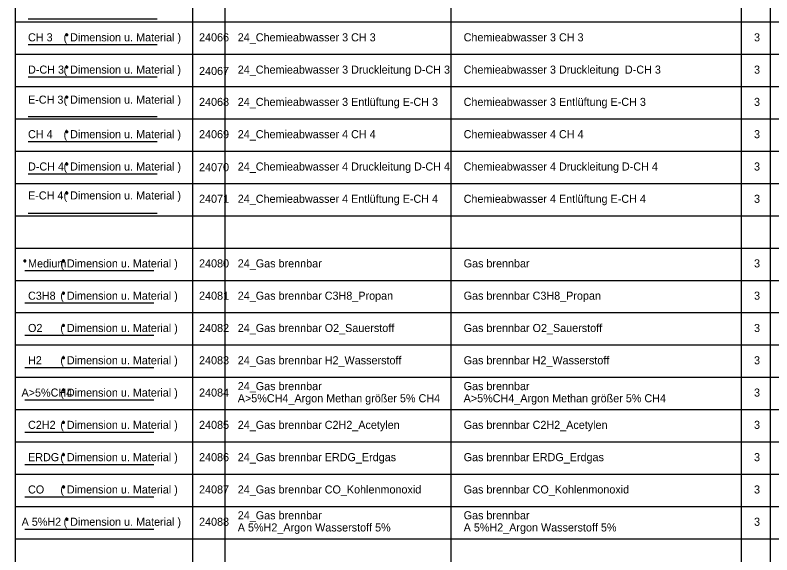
# Model space of a CAD drawing. Extents: x -14.5 to 23.8, y -56.3 to 8.
# Drawn here: x 0 to 11.73, y -23.75 to -15.39 of the extents above; entities that cross this region are included whole.
import ezdxf

# ---------------------------------------------------------------- set-up
doc = ezdxf.new("R2010")
doc.units = 0
for name, color, linetype in [('24_Chemieabwasser 2 Entlüftung E-CH2', 7, 'Continuous'), ('24_Chemieabwasser 3 CH 3', 7, 'Continuous'), ('24_Chemieabwasser 3 Druckleitung D-CH 3', 7, 'Continuous'), ('24_Chemieabwasser 3 Entlüftung E-CH 3', 7, 'Continuous'), ('24_Chemieabwasser 4 CH 4', 7, 'Continuous'), ('24_Chemieabwasser 4 Druckleitung CH 4', 7, 'Continuous'), ('24_Chemieabwasser 4 Entlüftung E-CH 4', 7, 'Continuous'), ('24_Gas brennbar', 7, 'Continuous'), ('24_Gas brennbar A 5%H2_Argon Wasserstoff 5%', 7, 'Continuous'), ('24_Gas brennbar A-5%CH4_Argon Methan größer 5% CH4', 7, 'Continuous'), ('24_Gas brennbar C2H2_Acetylen', 7, 'Continuous'), ('24_Gas brennbar C3H8_Propan', 7, 'Continuous'), ('24_Gas brennbar CO_Kohlenmonoxid', 7, 'Continuous'), ('24_Gas brennbar ERDG_Erdgas', 7, 'Continuous'), ('24_Gas brennbar H2_Wasserstoff', 7, 'Continuous'), ('24_Gas brennbar O2_Sauerstoff', 7, 'Continuous'), ('Default', 7, 'Continuous')]:
    doc.layers.add(name, color=color, linetype=linetype)

msp = doc.modelspace()

# ---------------------------------------------------------------- linework, layer by layer
at = {"layer": '24_Chemieabwasser 2 Entlüftung E-CH2'}
msp.add_line((0.2, -15.451), (2.2, -15.451), dxfattribs=at)
at = {"layer": '24_Chemieabwasser 3 CH 3'}
for p, q in [((0.778, -15.7), (0.822, -15.7)), ((0.784, -15.684), (0.816, -15.716)), ((0.816, -15.684), (0.784, -15.716)), ((0.8, -15.678), (0.8, -15.722)), ((0.2, -15.85), (2.2, -15.85)), ((0.8, -16.178), (0.8, -16.222)), ((0.778, -16.2), (0.822, -16.2)), ((0.784, -16.184), (0.816, -16.216)), ((0.816, -16.184), (0.784, -16.216))]:
    msp.add_line(p, q, dxfattribs=at)
at = {"layer": '24_Chemieabwasser 3 Druckleitung D-CH 3'}
msp.add_line((0.2, -16.35), (2.2, -16.35), dxfattribs=at)
at = {"layer": '24_Chemieabwasser 3 Entlüftung E-CH 3'}
for p, q in [((0.784, -16.649), (0.816, -16.681)), ((0.816, -16.649), (0.784, -16.681)), ((0.8, -16.643), (0.8, -16.687)), ((0.778, -16.665), (0.822, -16.665)), ((0.2, -16.961), (2.2, -16.961))]:
    msp.add_line(p, q, dxfattribs=at)
at = {"layer": '24_Chemieabwasser 4 CH 4'}
for p, q in [((0.778, -17.2), (0.822, -17.2)), ((0.784, -17.184), (0.816, -17.216)), ((0.816, -17.184), (0.784, -17.216)), ((0.8, -17.178), (0.8, -17.222)), ((0.2, -17.35), (2.2, -17.35)), ((0.778, -17.7), (0.822, -17.7))]:
    msp.add_line(p, q, dxfattribs=at)
at = {"layer": '24_Chemieabwasser 4 Druckleitung CH 4'}
for p, q in [((0.784, -17.684), (0.816, -17.716)), ((0.816, -17.684), (0.784, -17.716)), ((0.8, -17.678), (0.8, -17.722)), ((0.2, -17.85), (2.2, -17.85))]:
    msp.add_line(p, q, dxfattribs=at)
at = {"layer": '24_Chemieabwasser 4 Entlüftung E-CH 4'}
for p, q in [((0.778, -18.148), (0.822, -18.148)), ((0.784, -18.133), (0.816, -18.164)), ((0.816, -18.133), (0.784, -18.164)), ((0.8, -18.126), (0.8, -18.17)), ((0.2, -18.458), (2.2, -18.458))]:
    msp.add_line(p, q, dxfattribs=at)
at = {"layer": '24_Gas brennbar'}
for p, q in [((0.128, -19.2), (0.172, -19.2)), ((0.134, -19.184), (0.166, -19.216)), ((0.166, -19.184), (0.134, -19.216)), ((0.15, -19.178), (0.15, -19.222)), ((0.728, -19.2), (0.772, -19.2)), ((0.734, -19.184), (0.766, -19.216)), ((0.766, -19.184), (0.734, -19.216)), ((0.75, -19.178), (0.75, -19.222)), ((0.15, -19.35), (2.15, -19.35))]:
    msp.add_line(p, q, dxfattribs=at)
at = {"layer": '24_Gas brennbar A 5%H2_Argon Wasserstoff 5%'}
for p, q in [((0.778, -23.2), (0.822, -23.2)), ((0.784, -23.184), (0.816, -23.216)), ((0.816, -23.184), (0.784, -23.216)), ((0.8, -23.178), (0.8, -23.222)), ((0.15, -23.35), (2.15, -23.35))]:
    msp.add_line(p, q, dxfattribs=at)
at = {"layer": '24_Gas brennbar A-5%CH4_Argon Methan größer 5% CH4'}
for p, q in [((0.729, -21.2), (0.773, -21.2)), ((0.735, -21.184), (0.767, -21.216)), ((0.767, -21.184), (0.735, -21.216)), ((0.751, -21.178), (0.751, -21.222)), ((0.15, -21.35), (2.15, -21.35))]:
    msp.add_line(p, q, dxfattribs=at)
at = {"layer": '24_Gas brennbar C2H2_Acetylen'}
for p, q in [((0.734, -21.684), (0.766, -21.716)), ((0.766, -21.684), (0.734, -21.716)), ((0.75, -21.678), (0.75, -21.722)), ((0.728, -21.7), (0.772, -21.7)), ((0.15, -21.85), (2.15, -21.85))]:
    msp.add_line(p, q, dxfattribs=at)
at = {"layer": '24_Gas brennbar C3H8_Propan'}
for p, q in [((0.728, -19.7), (0.772, -19.7)), ((0.734, -19.684), (0.766, -19.716)), ((0.766, -19.684), (0.734, -19.716)), ((0.75, -19.678), (0.75, -19.722)), ((0.15, -19.85), (2.15, -19.85))]:
    msp.add_line(p, q, dxfattribs=at)
at = {"layer": '24_Gas brennbar CO_Kohlenmonoxid'}
for p, q in [((0.728, -22.7), (0.772, -22.7)), ((0.734, -22.684), (0.766, -22.716)), ((0.766, -22.684), (0.734, -22.716)), ((0.75, -22.678), (0.75, -22.722)), ((0.15, -22.85), (2.15, -22.85))]:
    msp.add_line(p, q, dxfattribs=at)
at = {"layer": '24_Gas brennbar ERDG_Erdgas'}
for p, q in [((0.728, -22.2), (0.772, -22.2)), ((0.734, -22.184), (0.766, -22.216)), ((0.766, -22.184), (0.734, -22.216)), ((0.75, -22.178), (0.75, -22.222)), ((0.15, -22.35), (2.15, -22.35))]:
    msp.add_line(p, q, dxfattribs=at)
at = {"layer": '24_Gas brennbar H2_Wasserstoff'}
for p, q in [((0.728, -20.7), (0.772, -20.7)), ((0.734, -20.684), (0.766, -20.716)), ((0.766, -20.684), (0.734, -20.716)), ((0.75, -20.678), (0.75, -20.722)), ((0.15, -20.85), (2.15, -20.85))]:
    msp.add_line(p, q, dxfattribs=at)
at = {"layer": '24_Gas brennbar O2_Sauerstoff'}
for p, q in [((0.728, -20.2), (0.772, -20.2)), ((0.734, -20.184), (0.766, -20.216)), ((0.766, -20.184), (0.734, -20.216)), ((0.75, -20.178), (0.75, -20.222)), ((0.15, -20.35), (2.15, -20.35))]:
    msp.add_line(p, q, dxfattribs=at)
at = {"layer": 'Default'}
for p, q in [((0, 0), (0, -53.5)), ((2.75, 0), (2.75, -53.5)), ((3.25, 0), (3.25, -53.5)), ((6.75, 0), (6.75, -53.5)), ((11.25, 0), (11.25, -53.5)), ((11.7, -0.35), (11.7, -44.5)), ((0, -15.5), (16, -15.5)), ((0, -16), (16, -16)), ((0, -16.5), (16, -16.5)), ((0, -17), (16, -17)), ((0, -17.5), (16, -17.5)), ((0, -18), (16, -18)), ((0, -18.5), (16, -18.5)), ((0, -19), (16, -19)), ((0, -19.5), (16, -19.5)), ((0, -20), (16, -20)), ((0, -20.5), (16, -20.5)), ((0, -21), (16, -21)), ((0, -21.5), (16, -21.5)), ((0, -22), (16, -22)), ((0, -22.5), (16, -22.5)), ((0, -23), (16, -23)), ((0, -23.5), (16, -23.5))]:
    msp.add_line(p, q, dxfattribs=at)

# ---------------------------------------------------------------- texts
at = {"layer": '24_Chemieabwasser 3 CH 3'}
for s, p in [('CH 3', (0.2, -15.8)), ('( Dimension u. Material )', (0.75, -15.8))]:
    msp.add_text(s, height=0.125, dxfattribs=at).set_placement(p)
at = {"layer": '24_Chemieabwasser 3 Druckleitung D-CH 3'}
for s, p in [('D-CH 3', (0.2, -16.3)), ('( Dimension u. Material )', (0.75, -16.3))]:
    msp.add_text(s, height=0.125, dxfattribs=at).set_placement(p)
at = {"layer": '24_Chemieabwasser 3 Entlüftung E-CH 3'}
for s, p in [('E-CH 3', (0.2, -16.765)), ('( Dimension u. Material )', (0.75, -16.765))]:
    msp.add_text(s, height=0.125, dxfattribs=at).set_placement(p)
at = {"layer": '24_Chemieabwasser 4 CH 4'}
for s, p in [('CH 4', (0.2, -17.3)), ('( Dimension u. Material )', (0.75, -17.3))]:
    msp.add_text(s, height=0.125, dxfattribs=at).set_placement(p)
at = {"layer": '24_Chemieabwasser 4 Druckleitung CH 4'}
for s, p in [('D-CH 4', (0.2, -17.8)), ('( Dimension u. Material )', (0.75, -17.8))]:
    msp.add_text(s, height=0.125, dxfattribs=at).set_placement(p)
at = {"layer": '24_Chemieabwasser 4 Entlüftung E-CH 4'}
for s, p in [('E-CH 4', (0.2, -18.248)), ('( Dimension u. Material )', (0.75, -18.248))]:
    msp.add_text(s, height=0.125, dxfattribs=at).set_placement(p)
at = {"layer": '24_Gas brennbar'}
for s, p in [('Medium', (0.2, -19.3)), ('( Dimension u. Material )', (0.7, -19.3))]:
    msp.add_text(s, height=0.125, dxfattribs=at).set_placement(p)
at = {"layer": '24_Gas brennbar A 5%H2_Argon Wasserstoff 5%'}
for s, p in [('A 5%H2', (0.1, -23.3)), ('( Dimension u. Material )', (0.75, -23.3))]:
    msp.add_text(s, height=0.125, dxfattribs=at).set_placement(p)
at = {"layer": '24_Gas brennbar A-5%CH4_Argon Methan größer 5% CH4'}
for s, p in [('A>5%CH4', (0.099, -21.3)), ('( Dimension u. Material )', (0.7, -21.3))]:
    msp.add_text(s, height=0.125, dxfattribs=at).set_placement(p)
at = {"layer": '24_Gas brennbar C2H2_Acetylen'}
for s, p in [('C2H2', (0.2, -21.8)), ('( Dimension u. Material )', (0.7, -21.8))]:
    msp.add_text(s, height=0.125, dxfattribs=at).set_placement(p)
at = {"layer": '24_Gas brennbar C3H8_Propan'}
for s, p in [('C3H8', (0.2, -19.8)), ('( Dimension u. Material )', (0.7, -19.8))]:
    msp.add_text(s, height=0.125, dxfattribs=at).set_placement(p)
at = {"layer": '24_Gas brennbar CO_Kohlenmonoxid'}
for s, p in [('CO', (0.2, -22.8)), ('( Dimension u. Material )', (0.7, -22.8))]:
    msp.add_text(s, height=0.125, dxfattribs=at).set_placement(p)
at = {"layer": '24_Gas brennbar ERDG_Erdgas'}
for s, p in [('ERDG', (0.2, -22.3)), ('( Dimension u. Material )', (0.7, -22.3))]:
    msp.add_text(s, height=0.125, dxfattribs=at).set_placement(p)
at = {"layer": '24_Gas brennbar H2_Wasserstoff'}
for s, p in [('H2', (0.2, -20.8)), ('( Dimension u. Material )', (0.7, -20.8))]:
    msp.add_text(s, height=0.125, dxfattribs=at).set_placement(p)
at = {"layer": '24_Gas brennbar O2_Sauerstoff'}
for s, p in [('( Dimension u. Material )', (0.7, -20.3)), ('O2', (0.2, -20.3))]:
    msp.add_text(s, height=0.125, dxfattribs=at).set_placement(p)
at = {"layer": 'Default'}
for s, p in [('24066', (2.85, -15.8)), ('24_Chemieabwasser 3 CH 3', (3.45, -15.8)), ('Chemieabwasser 3 CH 3', (6.95, -15.8)), ('3', (11.45, -15.8)), ('24_Chemieabwasser 3 Druckleitung D-CH 3', (3.45, -16.3)), ('Chemieabwasser 3 Druckleitung  D-CH 3', (6.95, -16.3)), ('3', (11.45, -16.3)), ('24067', (2.85, -16.321)), ('24068', (2.85, -16.8)), ('24_Chemieabwasser 3 Entlüftung E-CH 3', (3.45, -16.8)), ('Chemieabwasser 3 Entlüftung E-CH 3', (6.95, -16.8)), ('3', (11.45, -16.8)), ('24069', (2.85, -17.3)), ('24_Chemieabwasser 4 CH 4', (3.45, -17.3)), ('Chemieabwasser 4 CH 4', (6.95, -17.3)), ('3', (11.45, -17.3)), ('24070', (2.85, -17.811)), ('24_Chemieabwasser 4 Druckleitung D-CH 4', (3.45, -17.8)), ('Chemieabwasser 4 Druckleitung D-CH 4', (6.95, -17.8)), ('3', (11.45, -17.8)), ('24071', (2.85, -18.3)), ('24_Chemieabwasser 4 Entlüftung E-CH 4', (3.45, -18.3)), ('Chemieabwasser 4 Entlüftung E-CH 4', (6.95, -18.3)), ('3', (11.45, -18.3)), ('24080', (2.85, -19.3)), ('24_Gas brennbar', (3.45, -19.3)), ('Gas brennbar', (6.95, -19.3)), ('3', (11.45, -19.3)), ('24081', (2.85, -19.8)), ('24_Gas brennbar C3H8_Propan', (3.45, -19.8)), ('Gas brennbar C3H8_Propan', (6.95, -19.8)), ('3', (11.45, -19.8)), ('24_Gas brennbar O2_Sauerstoff', (3.45, -20.3)), ('Gas brennbar O2_Sauerstoff', (6.95, -20.3)), ('24082', (2.85, -20.3)), ('3', (11.45, -20.3)), ('24083', (2.85, -20.8)), ('24_Gas brennbar H2_Wasserstoff', (3.45, -20.8)), ('Gas brennbar H2_Wasserstoff', (6.95, -20.8)), ('3', (11.45, -20.8)), ('24_Gas brennbar', (3.45, -21.2)), ('Gas brennbar', (6.95, -21.2)), ('24084', (2.85, -21.3)), ('3', (11.45, -21.3)), ('A>5%CH4_Argon Methan größer 5% CH4', (3.45, -21.388)), ('A>5%CH4_Argon Methan größer 5% CH4', (6.95, -21.388)), ('24085', (2.85, -21.8)), ('24_Gas brennbar C2H2_Acetylen', (3.45, -21.8)), ('Gas brennbar C2H2_Acetylen', (6.95, -21.8)), ('3', (11.45, -21.8)), ('24086', (2.85, -22.3)), ('24_Gas brennbar ERDG_Erdgas', (3.45, -22.3)), ('Gas brennbar ERDG_Erdgas', (6.95, -22.3)), ('3', (11.45, -22.3)), ('24087', (2.85, -22.8)), ('24_Gas brennbar CO_Kohlenmonoxid', (3.45, -22.8)), ('Gas brennbar CO_Kohlenmonoxid', (6.95, -22.8)), ('3', (11.45, -22.8)), ('24_Gas brennbar ', (3.45, -23.2)), ('Gas brennbar ', (6.95, -23.2)), ('24088', (2.85, -23.3)), ('3', (11.45, -23.3)), ('A 5%H2_Argon Wasserstoff 5%', (3.45, -23.388)), ('A 5%H2_Argon Wasserstoff 5%', (6.95, -23.388))]:
    msp.add_text(s, height=0.125, dxfattribs=at).set_placement(p)

doc.saveas('drawing.dxf')
